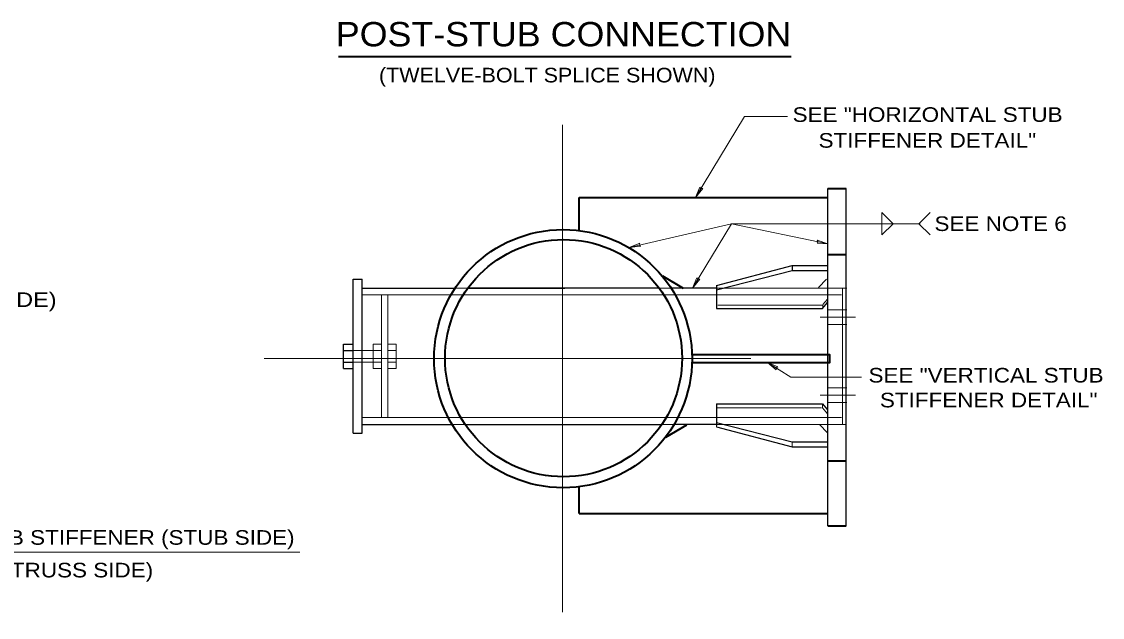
# Model space of a CAD drawing. Extents: x 312601.858 to 312602.699, y 144420.109 to 144420.704.
# Drawn here: x 312602.2309 to 312602.4529, y 144420.41 to 144420.5323 of the extents above; entities that cross this region are included whole.
import ezdxf
from ezdxf.enums import TextEntityAlignment as Align

# ---------------------------------------------------------------- set-up
doc = ezdxf.new("R2010")
doc.units = 0
doc.header["$LTSCALE"] = 0.0012
for name, pattern in [('DOT_DASHED', [7.7, 5, -1.2, 0.3, -1.2]), ('LONG_DASHED', [7.5, 6, -1.5]), ('MEDIUM_DASHED', [4.5, 3, -1.5]), ('SHORT_DASHED', [2.7, 1.5, -1.2])]:
    doc.linetypes.add(name, pattern=pattern)
doc.layers.add('1', color=7, linetype='Continuous', lineweight=13)
doc.layers.add('2', color=7, linetype='Continuous', lineweight=25)

msp = doc.modelspace()

# ---------------------------------------------------------------- linework, layer by layer
at = {"layer": '1', "lineweight": 40}
msp.add_line((312602.296, 144420.5251), (312602.389, 144420.5251), dxfattribs=at)
at = {"layer": '1'}
for p, q in [((312602.3693, 144420.4962), (312602.3794, 144420.5128)), ((312602.3794, 144420.5128), (312602.3882, 144420.5128)), ((312602.4076, 144420.4931), (312602.4099, 144420.4908)), ((312602.4076, 144420.4885), (312602.4076, 144420.4931)), ((312602.4152, 144420.4908), (312602.4175, 144420.4931)), ((312602.3687, 144420.4776), (312602.3767, 144420.4908)), ((312602.3767, 144420.4908), (312602.3965, 144420.4867)), ((312602.4076, 144420.4885), (312602.4099, 144420.4908)), ((312602.4152, 144420.4908), (312602.4175, 144420.4885)), ((312602.3889, 144420.4593), (312602.3841, 144420.4623)), ((312602.3889, 144420.4593), (312602.4034, 144420.4593)), ((312602.3008, 144420.4481), (312602.3008, 144420.4485)), ((312602.3892, 144420.4449), (312602.3892, 144420.4461)), ((312602.3965, 144420.4313), (312602.3965, 144420.4317)), ((312602.288, 144420.4234), (312602.1806, 144420.4234))]:
    msp.add_line(p, q, dxfattribs=at)
at = {"layer": '1', "linetype": 'DOT_DASHED'}
for p, q in [((312602.342, 144420.5111), (312602.342, 144420.41)), ((312602.3949, 144420.4716), (312602.4022, 144420.4716)), ((312602.2807, 144420.4631), (312602.4189, 144420.4631)), ((312602.3949, 144420.4556), (312602.4022, 144420.4556))]:
    msp.add_line(p, q, dxfattribs=at)
at = {"layer": '1', "lineweight": 25}
for p, q in [((312602.3965, 144420.4288), (312602.3965, 144420.498)), ((312602.4003, 144420.4288), (312602.4003, 144420.498)), ((312602.3736, 144420.4781), (312602.3892, 144420.4822)), ((312602.3892, 144420.4822), (312602.3964, 144420.4822)), ((312602.3892, 144420.4822), (312602.3892, 144420.4811)), ((312602.299, 144420.4478), (312602.299, 144420.4794)), ((312602.299, 144420.4794), (312602.3008, 144420.4794)), ((312602.3008, 144420.4478), (312602.3008, 144420.4794)), ((312602.3008, 144420.4776), (312602.3199, 144420.4776)), ((312602.3618, 144420.4776), (312602.3225, 144420.4776)), ((312602.3226, 144420.4776), (312602.3425, 144420.4776)), ((312602.3736, 144420.4776), (312602.3643, 144420.4776)), ((312602.3736, 144420.4781), (312602.3736, 144420.4734)), ((312602.3736, 144420.4734), (312602.3954, 144420.4734)), ((312602.3954, 144420.4734), (312602.3964, 144420.4746)), ((312602.297, 144420.4611), (312602.297, 144420.4661)), ((312602.297, 144420.4661), (312602.299, 144420.4661)), ((312602.297, 144420.4648), (312602.299, 144420.4648)), ((312602.297, 144420.4624), (312602.299, 144420.4624)), ((312602.297, 144420.4611), (312602.299, 144420.4611)), ((312602.3736, 144420.4538), (312602.3736, 144420.4494)), ((312602.3736, 144420.4538), (312602.3954, 144420.4538)), ((312602.3954, 144420.4538), (312602.3964, 144420.4526)), ((312602.3008, 144420.4496), (312602.3193, 144420.4496)), ((312602.322, 144420.4496), (312602.3624, 144420.4496)), ((312602.3736, 144420.4496), (312602.3649, 144420.4496)), ((312602.3736, 144420.4491), (312602.3892, 144420.445)), ((312602.299, 144420.4478), (312602.3008, 144420.4478)), ((312602.3892, 144420.445), (312602.3964, 144420.445))]:
    msp.add_line(p, q, dxfattribs=at)
at = {"layer": '1', "lineweight": 35}
for p, q in [((312602.3965, 144420.498), (312602.4003, 144420.498)), ((312602.3454, 144420.4962), (312602.3965, 144420.4962)), ((312602.3454, 144420.4894), (312602.3454, 144420.4962)), ((312602.3965, 144420.4845), (312602.4003, 144420.4845)), ((312602.3625, 144420.4801), (312602.3668, 144420.4776)), ((312602.3632, 144420.447), (312602.3675, 144420.4495)), ((312602.3965, 144420.4421), (312602.4003, 144420.4421)), ((312602.3454, 144420.4313), (312602.3454, 144420.4367)), ((312602.3454, 144420.4313), (312602.3965, 144420.4313)), ((312602.3965, 144420.4288), (312602.4003, 144420.4288))]:
    msp.add_line(p, q, dxfattribs=at)
at = {"layer": '1', "linetype": 'LONG_DASHED'}
for p, q in [((312602.3199, 144420.4776), (312602.3225, 144420.4776)), ((312602.3618, 144420.4776), (312602.3643, 144420.4776)), ((312602.4004, 144420.4776), (312602.3737, 144420.4776)), ((312602.3962, 144420.4794), (312602.3946, 144420.4777)), ((312602.3995, 144420.4776), (312602.3995, 144420.4636)), ((312602.3008, 144420.4762), (312602.3993, 144420.4762)), ((312602.3048, 144420.4762), (312602.3048, 144420.451)), ((312602.3061, 144420.4762), (312602.3061, 144420.451)), ((312602.3955, 144420.4742), (312602.3964, 144420.4753)), ((312602.3954, 144420.4741), (312602.3739, 144420.4741)), ((312602.3955, 144420.4734), (312602.3955, 144420.4741)), ((312602.3995, 144420.4496), (312602.3995, 144420.4636)), ((312602.3736, 144420.4491), (312602.3736, 144420.4538)), ((312602.3952, 144420.453), (312602.3737, 144420.453)), ((312602.3954, 144420.453), (312602.3954, 144420.4537)), ((312602.3954, 144420.453), (312602.3964, 144420.4518)), ((312602.3954, 144420.453), (312602.3964, 144420.4518)), ((312602.3008, 144420.451), (312602.3993, 144420.451)), ((312602.3166, 144420.4496), (312602.3221, 144420.4496)), ((312602.3625, 144420.4496), (312602.3651, 144420.4496)), ((312602.4003, 144420.4496), (312602.3738, 144420.4496)), ((312602.3964, 144420.4479), (312602.3948, 144420.4496))]:
    msp.add_line(p, q, dxfattribs=at)
at = {"layer": '1', "linetype": 'SHORT_DASHED'}
for p, q in [((312602.3964, 144420.4731), (312602.4004, 144420.4731)), ((312602.3964, 144420.4701), (312602.4004, 144420.4701)), ((312602.3964, 144420.4571), (312602.4004, 144420.4571)), ((312602.3964, 144420.4541), (312602.4004, 144420.4541))]:
    msp.add_line(p, q, dxfattribs=at)
at = {"layer": '1', "linetype": 'MEDIUM_DASHED'}
for p, q in [((312602.299, 144420.4648), (312602.3048, 144420.4648)), ((312602.3031, 144420.4661), (312602.3031, 144420.4611)), ((312602.3031, 144420.4661), (312602.3048, 144420.4661)), ((312602.3061, 144420.4661), (312602.3078, 144420.4661)), ((312602.3061, 144420.4648), (312602.3078, 144420.4648)), ((312602.3078, 144420.4661), (312602.3078, 144420.4611)), ((312602.299, 144420.4624), (312602.3048, 144420.4624)), ((312602.3061, 144420.4624), (312602.3078, 144420.4624)), ((312602.3031, 144420.4611), (312602.3048, 144420.4611)), ((312602.3061, 144420.4611), (312602.3078, 144420.4611))]:
    msp.add_line(p, q, dxfattribs=at)
at = {"layer": '1'}
for points in [[(312602.3708, 144420.498), (312602.3693, 144420.4962), (312602.3702, 144420.4983), (312602.3704, 144420.498)], [(312602.3581, 144420.4862), (312602.3557, 144420.4859), (312602.3579, 144420.4868), (312602.3577, 144420.4864)], [(312602.3943, 144420.4874), (312602.3965, 144420.4867), (312602.3943, 144420.4868), (312602.3945, 144420.4871)], [(312602.3702, 144420.4794), (312602.3687, 144420.4776), (312602.3696, 144420.4797), (312602.3698, 144420.4794)], [(312602.3859, 144420.4608), (312602.3841, 144420.4623), (312602.3862, 144420.4614), (312602.3859, 144420.4612)]]:
    msp.add_lwpolyline(points, close=True, dxfattribs=at)
msp.add_lwpolyline([(312602.3557, 144420.4859), (312602.3767, 144420.4908), (312602.4155, 144420.4908)], dxfattribs=at)
at = {"layer": '1', "lineweight": 25}
for points in [[(312602.3736, 144420.4772), (312602.3892, 144420.4812), (312602.3964, 144420.4812)], [(312602.3736, 144420.45), (312602.3892, 144420.446), (312602.3964, 144420.446)]]:
    msp.add_lwpolyline(points, dxfattribs=at)
at = {"layer": '1', "lineweight": 35}
msp.add_lwpolyline([(312602.3686, 144420.4623), (312602.3969, 144420.4623), (312602.3969, 144420.4639), (312602.3686, 144420.4639)], close=True, dxfattribs=at)
for centre, radius in [((312602.3421, 144420.4631), 0.0265), ((312602.3422, 144420.4632), 0.02435)]:
    msp.add_circle(centre, radius, dxfattribs=at)

# ---------------------------------------------------------------- texts
at = {"layer": '2'}
for s, height, width, p in [('POST-STUB CONNECTION', 0.005, 1.1, (312602.3422, 144420.5272)), ('(TWELVE-BOLT SPLICE SHOWN)', 0.003, 1.1, (312602.33885, 144420.5198)), ('SEE "HORIZONTAL STUB', 0.003, 1.15, (312602.417, 144420.5117)), ('STIFFENER DETAIL"', 0.003, 1.15, (312602.41695, 144420.5064)), ('SEE NOTE 6', 0.003, 1.15, (312602.432, 144420.4893)), ('L VERTICAL STUB STIFFENER (STUB SIDE)', 0.003, 1.2, (312602.18815, 144420.4737)), ('SEE "VERTICAL STUB', 0.003, 1.15, (312602.429, 144420.4582)), ('STIFFENER DETAIL"', 0.003, 1.15, (312602.42955, 144420.4531)), ('L HORIZONTAL STUB STIFFENER (STUB SIDE)', 0.003, 1.15, (312602.23555, 144420.4249)), ('L BRACKET PLATE (TRUSS SIDE)', 0.003, 1.15, (312602.2211, 144420.4182))]:
    msp.add_text(s, height=height, dxfattribs=dict(at, width=width)).set_placement(p, align=Align.CENTER)

doc.saveas('drawing.dxf')
